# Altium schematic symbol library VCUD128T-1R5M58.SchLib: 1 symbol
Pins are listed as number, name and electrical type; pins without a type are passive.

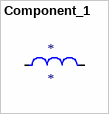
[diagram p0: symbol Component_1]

## Component_1
designator *
Manufacturer Part Number: VCUD128T-1R5M58; Value: 1.5uH; Isat: 46.7A; DCR_ohm: 1.45; Ind_H: 1.5
footprint PCBComponent_1
pins: 1, 2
